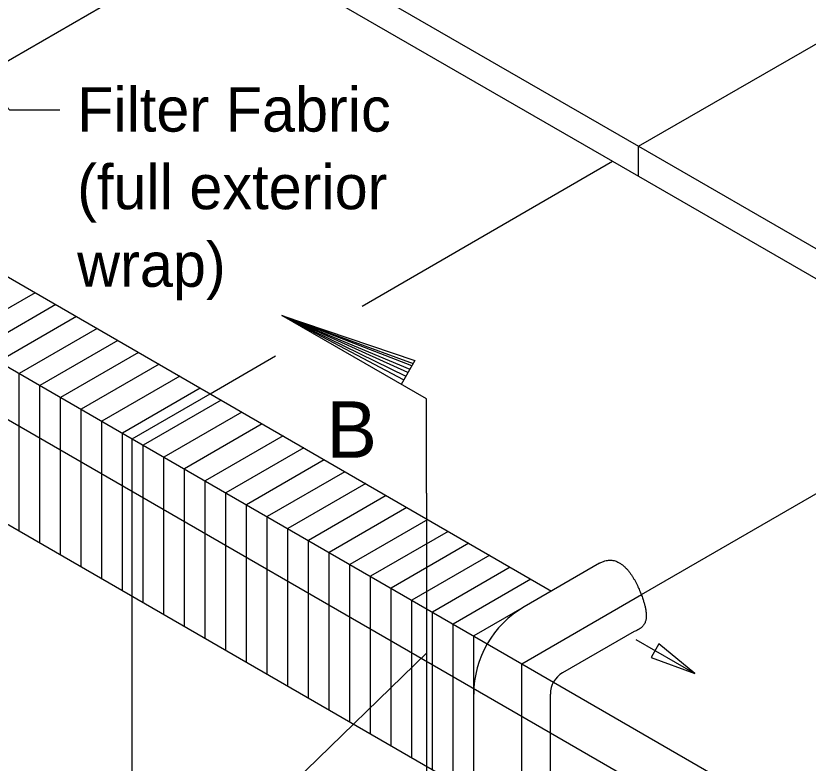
# Model space of a CAD drawing. Extents: x 0 to 123, y 0 to 78.
# Drawn here: x 18.09 to 28.88, y 55.54 to 65.71 of the extents above; entities that cross this region are included whole.
import ezdxf

# ---------------------------------------------------------------- set-up
doc = ezdxf.new("R2010")
doc.units = 0
for name, color, linetype in [('Dimension', 7, 'Continuous'), ('Miscellaneous', 7, 'Continuous'), ('SubStrConc', 7, 'Continuous'), ('SubStrConc_h', 7, 'Continuous'), ('TextStructures', 7, 'Continuous')]:
    doc.layers.add(name, color=color, linetype=linetype)

msp = doc.modelspace()

# ---------------------------------------------------------------- linework, layer by layer
at = {"layer": 'Dimension'}
for p, q in [((23.37, 60.756), (21.711, 61.632)), ((21.711, 61.632), (23.4, 60.808)), ((23.427, 60.855), (21.711, 61.632)), ((21.711, 61.632), (23.455, 60.903)), ((23.48, 60.946), (21.711, 61.632)), ((21.711, 61.632), (23.5, 60.981)), ((23.679, 60.496), (21.711, 61.632)), ((21.711, 61.632), (23.522, 61.02)), ((23.522, 61.02), (23.335, 60.695)), ((23.679, 59.212), (23.679, 60.496)), ((23.679, 59.212), (23.679, 54.858)), ((26.53, 57.221), (27.332, 56.758)), ((13.497, 47.131), (23.679, 57.035))]:
    msp.add_line(p, q, dxfattribs=at)
msp.add_lwpolyline([(16.913, 65.642), (18.002, 64.431), (18.691, 64.431)], dxfattribs=at)
msp.add_lwpolyline([(27.332, 56.758), (26.844, 57.162), (26.738, 56.978)], close=True, dxfattribs=at)
at = {"layer": 'Miscellaneous'}
for p, q in [((15.431, 63.629), (25.384, 57.882)), ((18.352, 61.942), (17.291, 61.33)), ((18.633, 61.78), (17.573, 61.168)), ((18.915, 61.618), (17.854, 61.005)), ((19.196, 61.455), (18.135, 60.843)), ((19.477, 61.293), (18.416, 60.68)), ((19.758, 61.13), (18.698, 60.518)), ((20.04, 60.968), (18.979, 60.356)), ((18.135, 58.7), (18.135, 60.843)), ((20.321, 60.806), (19.26, 60.193)), ((18.416, 58.537), (18.416, 60.68)), ((20.602, 60.643), (19.542, 60.031)), ((14.852, 60.595), (24.324, 55.127)), ((18.698, 58.375), (18.698, 60.518)), ((20.884, 60.481), (19.823, 59.868)), ((18.979, 58.212), (18.979, 60.356)), ((21.165, 60.318), (20.104, 59.706)), ((19.26, 58.05), (19.26, 60.193)), ((21.446, 60.156), (20.386, 59.544)), ((19.542, 57.888), (19.542, 60.031)), ((21.728, 59.994), (20.667, 59.381)), ((19.823, 57.725), (19.823, 59.868)), ((22.009, 59.831), (20.948, 59.219)), ((20.104, 57.563), (20.104, 59.706)), ((22.29, 59.669), (21.229, 59.056)), ((20.386, 57.4), (20.386, 59.544)), ((22.571, 59.506), (21.511, 58.894)), ((20.667, 57.238), (20.667, 59.381)), ((22.853, 59.344), (21.792, 58.732)), ((20.948, 57.076), (20.948, 59.219)), ((23.134, 59.182), (22.073, 58.569)), ((21.229, 56.913), (21.229, 59.056)), ((23.415, 59.019), (22.355, 58.407)), ((21.511, 56.751), (21.511, 58.894)), ((23.697, 58.857), (22.636, 58.244)), ((21.792, 56.588), (21.792, 58.732)), ((23.978, 58.694), (22.917, 58.082)), ((22.073, 56.426), (22.073, 58.569)), ((24.259, 58.532), (23.199, 57.92)), ((22.355, 56.264), (22.355, 58.407)), ((24.541, 58.369), (23.48, 57.757)), ((26.038, 58.26), (25.01, 57.666)), ((22.636, 56.101), (22.636, 58.244)), ((24.822, 58.207), (23.761, 57.595)), ((22.917, 55.939), (22.917, 58.082)), ((25.103, 58.045), (24.042, 57.432)), ((23.199, 55.776), (23.199, 57.92)), ((23.48, 55.614), (23.48, 57.757)), ((25.01, 57.666), (24.324, 57.27)), ((23.761, 55.451), (23.761, 57.595)), ((24.042, 55.289), (24.042, 57.432)), ((26.506, 57.331), (25.533, 56.769)), ((24.324, 56.478), (24.324, 57.27)), ((24.324, 54.371), (24.324, 56.478)), ((25.367, 54.391), (25.367, 56.48))]:
    msp.add_line(p, q, dxfattribs=at)
for centre, radius in [((25.696, 56.478), 1.372), ((25.7, 56.48), 0.333)]:
    msp.add_arc(centre, radius, 120, 180, dxfattribs=at)
msp.add_open_spline([(26.038, 58.26), (26.221, 58.365), (26.476, 58.17), (26.606, 57.837), (26.698, 57.6), (26.674, 57.384), (26.506, 57.331)], degree=4, dxfattribs=at)
at = {"layer": 'SubStrConc'}
for p, q in [((26.568, 63.935), (33.109, 67.711)), ((21.265, 66.997), (26.568, 63.935)), ((15.426, 63.626), (20.911, 66.793)), ((20.911, 66.793), (26.215, 63.731)), ((26.568, 63.935), (31.871, 60.873)), ((26.568, 63.527), (26.568, 63.935)), ((22.803, 61.761), (26.215, 63.731)), ((26.215, 63.731), (31.518, 60.669)), ((20.735, 60.567), (21.625, 61.081)), ((26.607, 57.833), (31.518, 60.669)), ((19.674, 52.402), (19.674, 57.811)), ((25.409, 56.643), (29.012, 54.563)), ((25.367, 55.953), (28.394, 54.206))]:
    msp.add_line(p, q, dxfattribs=at)
at = {"layer": 'SubStrConc_h'}
for p, q in [((9.067, 65.364), (25.367, 55.953)), ((15.426, 62.407), (19.674, 59.954)), ((19.674, 59.954), (20.735, 60.567)), ((19.674, 59.954), (24.977, 56.893)), ((19.674, 57.811), (19.674, 59.954)), ((24.977, 56.893), (26.607, 57.833)), ((24.977, 56.893), (25.409, 56.643)), ((24.977, 54.092), (24.977, 56.893))]:
    msp.add_line(p, q, dxfattribs=at)

# ---------------------------------------------------------------- texts
at = {"layer": 'Dimension'}
for s, p in [('Filter Fabric', (18.925, 64.135)), ('(full exterior', (18.925, 63.079)), ('wrap)', (18.925, 62.023))]:
    msp.add_text(s, height=0.6048, dxfattribs=at).set_placement(p)
at = {"layer": 'TextStructures'}
msp.add_text('B', height=0.768, dxfattribs=at).set_placement((22.321, 59.696))

doc.saveas('drawing.dxf')
